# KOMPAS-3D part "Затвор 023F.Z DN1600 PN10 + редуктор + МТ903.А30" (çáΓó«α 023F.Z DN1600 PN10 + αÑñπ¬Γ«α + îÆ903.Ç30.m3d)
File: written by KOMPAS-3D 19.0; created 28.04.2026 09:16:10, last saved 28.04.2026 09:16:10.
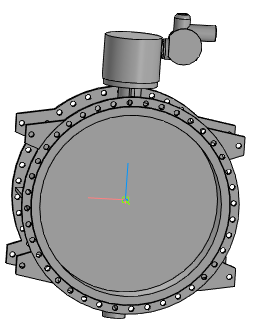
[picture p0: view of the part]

Document properties: Автор: Энергия; Полное имя файла: ..\..\Затвор 023F.Z DN400-DN1600 + редуктор + МТ903\Затвор 023F.Z DN1600 PN10 + редуктор + МТ903.А30.a3d

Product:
- Part/product: Затвор 023F.Z DN1600 PN10 + редуктор + МТ903.А30
    Масса: 4382.95

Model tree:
1. Операция без истории:1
